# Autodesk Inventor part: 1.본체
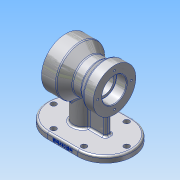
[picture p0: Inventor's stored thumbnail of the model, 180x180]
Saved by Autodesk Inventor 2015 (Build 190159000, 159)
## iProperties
Created: 2020-01
Part Number: 1.본체
Material: 알루미늄 6061
Document SubType Name: Modeling
Designer: user
Density: 2.7 g/cm^3
Appearance: 알루미늄 - 평지
Mass: 938.108 g
Surface Area: 654.889 cm^2
Volume: 347.447 cm^3
Author: user
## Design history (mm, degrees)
sketch "스케치1"
  geometry: L1 (-40, 0)-(40, 0); L2 (-40, 26)-(-40, 40); L3 (-40, 40)-(-16, 40); L4 (-16, 40)-(-1.103, 27.5); L5 (-1.103, 27.5)-(13.289, 27.5); L6 (13.289, 27.5)-(24, 35); L7 (24, 35)-(40, 35); L8 (40, 35)-(40, 20); L9 (-40, 26)-(-20, 26); L10 (-20, 26)-(-20, 16); L11 (-20, 16)-(23, 16); L12 (23, 16)-(23, 20); L13 (23, 20)-(40, 20); 2 further points
  constraints: 26 end point, 7 perpendicular, 2 parallel, 2 vertical alignment, 1 coincident, 1 horizontal, 1 midpoint, 1 vertical
  dimensions: "d4" = 35 deg angle of L5 L6; "d5" = 40 deg angle of L4 L5; "d6" = 24 distance of L2.end L3.end; "d7" = 16 distance of L6.end L7.end; "d8" = 80 distance between parallel lines of L8 L2; "d9" = 80 diameter of L3 L1; "d10" = 55 diameter of L5 L1; "d11" = 70 diameter of L7 L1; "d12" = 20 distance of L2.start L9.end; "d14" = 52 diameter of L9 L1; "d15" = 32 diameter of L11 L1; "d16" = 40 diameter of L13 L1; "d17" = 17 distance of L8.end L12.end
revolve "회전1" sketch "스케치1" stored, may be unused: angle "d18" = 90 deg
node "작업 평면1"
sketch "스케치2"
  geometry: L1 (25, 0)-(-25, 0); L2 (25, 45)-(-25, 45); L3 (-25, -45)-(25, -45); A1 r 45 centre (25, 0) between (25, -45) and (25, 45); A2 r 45 centre (-25, 0) between (-25, 45) and (-25, -45); 1 further point
  constraints: 8 end point, 4 point on circle, 4 tangent, 2 centre point, 1 horizontal, 1 midpoint, 1 parallel
  dimensions: "d20" = 50 distance of L1.start L1.end; "d21" = 45 radius of A1
extrude "돌출1" join sketch "스케치2" distance "d22" = 10; taper "d23" = 0 deg
sketch "스케치3"
  geometry: L1 (-70, 0)-(-12, 0); C1 r 16 at (-12, 0); A1 r 45 centre (-25, 0) between (-25, 45) and (-25, -45) reference; 1 further point
  constraints: 2 end point, 1 centre point, 1 coincident, 1 horizontal, 1 point on circle
  dimensions: "d24" = 58 distance of L1.start L1.end; "d25" = 32 diameter of C1
extrude "돌출2" join sketch "스케치3" stored distance "d26" = 10; taper "d27" = 0 deg
sketch "스케치4" dims "d28" = 55
  geometry: C1 r 35 at (0, 0) reference; C2 r 20 at (0, 0) reference; 2 further points
  constraints: 2 vertical alignment, 1 coincident, 2 other
hole "구멍1" sketch "스케치4" at (0, 27.5) diameter "d29" = 3.242; stored, may be unused: countersink angle "d33" = 90 deg, drill point angle "d35" = 118 deg; dims "d30" = 9, "d31" = 4, "d32" = 2, "d34" = 11
sketch "스케치5"
  geometry: L1 (40, -35)-(40, 35) reference; L2 (24, -35)-(40, -35) reference; L3 (25, -70)-(-25, -70) reference; L4 (70, -70)-(25, -70) reference; L5 (30, -35)-(30, -70); 1 further point
  constraints: 2 end point, 2 point on line, 1 perpendicular
  dimensions: "d39" = 10 distance between parallel lines of L1 L5
feature "리브1" sketch "스케치5" dims "d40" = 1, "d41" = 10, "d42" = 0, "d43" = 0, "d44" = 1, "d45" = 1
sketch "스케치6"
  geometry: L1 (3.199, 5)-(30, 5) reference; L2 (-25, -45)-(25, -45) reference; L3 (-25, 0)-(25, 0); L4 (-25, -35)-(25, -35); L5 (25, 35)-(-25, 35); A1 r 45 centre (25, 0) between (25, -45) and (25, 45) reference; A2 r 35 centre (-25, 0) between (-25, 35) and (-25, -35); A3 r 35 centre (25, 0) between (25, -35) and (25, 35); 7 further points
  constraints: 8 end point, 7 point on circle, 4 tangent, 3 coincident, 2 centre point, 2 parallel, 1 midpoint
  dimensions: "d46" = 10 distance between parallel lines of L2 L4
hole "구멍2" sketch "스케치6" at (-60, 0), (60, 0), (25, -35), (25, 35), (-25, -35), (-25, 35) diameter "d47" = 9; stored, may be unused: countersink angle "d51" = 90 deg, drill point angle "d53" = 118 deg; dims "d48" = 8.608, "d49" = 4, "d50" = 2, "d52" = 15.664
sketch "스케치7" dims "d54" = 66
  geometry: C1 r 26 at (0, 0) reference; C2 r 40 at (0, 0) reference; 2 further points
  constraints: 2 horizontal alignment, 1 coincident, 2 other
hole "구멍3" sketch "스케치7" at (-33, 0) diameter "d55" = 3.242; stored, may be unused: countersink angle "d59" = 90 deg, drill point angle "d61" = 118 deg; dims "d56" = 9, "d57" = 4, "d58" = 2, "d60" = 11
fillet "모깎기1" dims "d65" = 0.3
fillet "모깎기2" dims "d66" = 3
fillet "모깎기3" dims "d67" = 3
fillet "모깎기4" dims "d68" = 3
chamfer "모따기1" distance "d69" = 1; stored, may be unused: second distance "d70" = 2, angle "d71" = 45 deg
chamfer "모따기2" distance "d72" = 1; stored, may be unused: second distance "d73" = 2, angle "d74" = 45 deg
node "작업 평면2"
sketch "스케치8"
  geometry: L1 (95, 0)-(50, 0) reference; L2 (-45, 0)-(-45, 7) reference; 2 further points
  constraints: 1 other
  dimensions: "d76" = 4 distance from line of L1 point (25, 4); "d77" = 70 distance from line of point (25, 4) L2
feature "엠보싱1" sketch "스케치8" dims "d20" = 50, "d21" = 45, "d78" = 0.5, "d79" = 0
node "솔리드1"
pattern_circular "원형 패턴1" dims angle "d37" = 360 deg
pattern_circular "원형 패턴2" dims angle "d63" = 360 deg
other parameters: "d75" = 11.75
